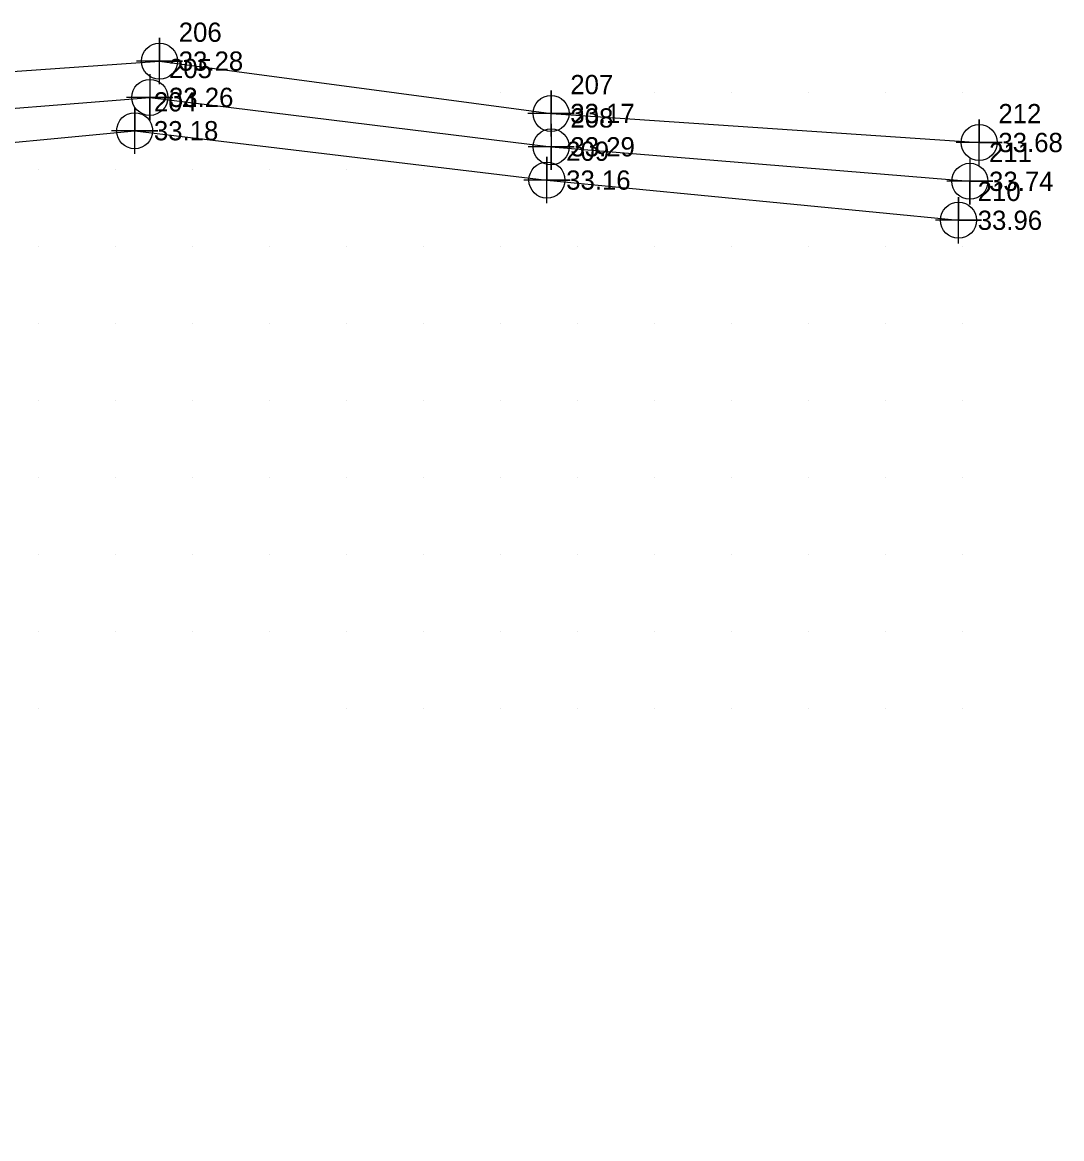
# Model space of a CAD drawing. Extents: x 2204340 to 2204783, y 268170 to 268760.
# Drawn here: x 2204647.9 to 2204782.9, y 268494.2 to 268639.1 of the extents above; entities that cross this region are included whole.
import ezdxf

# ---------------------------------------------------------------- set-up
doc = ezdxf.new("R2010")
doc.units = 0
for name, color, linetype in [('Exist DTM Crownline', 7, 'Continuous'), ('Exist DTM Crownline Cogo Elevation', 7, 'Continuous'), ('Exist DTM Crownline Cogo Number', 7, 'Continuous'), ('Exist DTM Crownline Cogo Point CELL', 7, 'Continuous'), ('Exist DTM QL2 LIDAR Elevation Point', 7, 'Continuous'), ('Exist Roads Soil', 7, 'Continuous'), ('Exist Roads Soil Cogo Elevation', 7, 'Continuous'), ('Exist Roads Soil Cogo Number', 7, 'Continuous'), ('Exist Roads Soil Cogo Point CELL', 7, 'Continuous')]:
    doc.layers.add(name, color=color, linetype=linetype)

msp = doc.modelspace()

# ---------------------------------------------------------------- linework, layer by layer
at = {"layer": 'Exist DTM Crownline'}
msp.add_lwpolyline([(2204544.57, 268496.57), (2204544.8, 268497.2), (2204557.39, 268525.73), (2204578.98, 268570.95), (2204607.65, 268611.86), (2204633.94, 268626.95), (2204664.49, 268629.4), (2204716.63, 268622.98), (2204771.01, 268618.5)], dxfattribs=at)
at = {"layer": 'Exist DTM Crownline Cogo Point CELL'}
for points in [[(2204664.49, 268632.4), (2204664.49, 268626.4), (2204664.49, 268629.4), (2204667.49, 268629.4), (2204661.49, 268629.4)], [(2204716.63, 268625.98), (2204716.63, 268619.98), (2204716.63, 268622.98), (2204719.63, 268622.98), (2204713.63, 268622.98)], [(2204771.01, 268621.5), (2204771.01, 268615.5), (2204771.01, 268618.5), (2204774.01, 268618.5), (2204768.01, 268618.5)]]:
    msp.add_lwpolyline(points, dxfattribs=at)
for centre in [(2204664.49, 268629.4), (2204716.63, 268622.98), (2204771.01, 268618.5)]:
    msp.add_circle(centre, 2.34, dxfattribs=at)
at = {"layer": 'Exist DTM QL2 LIDAR Elevation Point'}
for p, q in [((2204710, 268630), (2204710, 268630)), ((2204720, 268630), (2204720, 268630)), ((2204730, 268630), (2204730, 268630)), ((2204740, 268630), (2204740, 268630)), ((2204750, 268630), (2204750, 268630)), ((2204760, 268630), (2204760, 268630)), ((2204770, 268630), (2204770, 268630)), ((2204650, 268620), (2204650, 268620)), ((2204660, 268620), (2204660, 268620)), ((2204670, 268620), (2204670, 268620)), ((2204680, 268620), (2204680, 268620)), ((2204690, 268620), (2204690, 268620)), ((2204700, 268620), (2204700, 268620)), ((2204650, 268610), (2204650, 268610)), ((2204660, 268610), (2204660, 268610)), ((2204670, 268610), (2204670, 268610)), ((2204680, 268610), (2204680, 268610)), ((2204690, 268610), (2204690, 268610)), ((2204700, 268610), (2204700, 268610)), ((2204710, 268610), (2204710, 268610)), ((2204720, 268610), (2204720, 268610)), ((2204730, 268610), (2204730, 268610)), ((2204740, 268610), (2204740, 268610)), ((2204750, 268610), (2204750, 268610)), ((2204760, 268610), (2204760, 268610)), ((2204770, 268610), (2204770, 268610)), ((2204650, 268600), (2204650, 268600)), ((2204660, 268600), (2204660, 268600)), ((2204670, 268600), (2204670, 268600)), ((2204680, 268600), (2204680, 268600)), ((2204690, 268600), (2204690, 268600)), ((2204700, 268600), (2204700, 268600)), ((2204710, 268600), (2204710, 268600)), ((2204720, 268600), (2204720, 268600)), ((2204730, 268600), (2204730, 268600)), ((2204740, 268600), (2204740, 268600)), ((2204750, 268600), (2204750, 268600)), ((2204760, 268600), (2204760, 268600)), ((2204770, 268600), (2204770, 268600)), ((2204650, 268590), (2204650, 268590)), ((2204660, 268590), (2204660, 268590)), ((2204670, 268590), (2204670, 268590)), ((2204680, 268590), (2204680, 268590)), ((2204690, 268590), (2204690, 268590)), ((2204700, 268590), (2204700, 268590)), ((2204710, 268590), (2204710, 268590)), ((2204720, 268590), (2204720, 268590)), ((2204730, 268590), (2204730, 268590)), ((2204740, 268590), (2204740, 268590)), ((2204750, 268590), (2204750, 268590)), ((2204760, 268590), (2204760, 268590)), ((2204770, 268590), (2204770, 268590)), ((2204650, 268580), (2204650, 268580)), ((2204660, 268580), (2204660, 268580)), ((2204670, 268580), (2204670, 268580)), ((2204680, 268580), (2204680, 268580)), ((2204690, 268580), (2204690, 268580)), ((2204700, 268580), (2204700, 268580)), ((2204710, 268580), (2204710, 268580)), ((2204720, 268580), (2204720, 268580)), ((2204730, 268580), (2204730, 268580)), ((2204740, 268580), (2204740, 268580)), ((2204750, 268580), (2204750, 268580)), ((2204760, 268580), (2204760, 268580)), ((2204770, 268580), (2204770, 268580)), ((2204650, 268570), (2204650, 268570)), ((2204660, 268570), (2204660, 268570)), ((2204670, 268570), (2204670, 268570)), ((2204680, 268570), (2204680, 268570)), ((2204690, 268570), (2204690, 268570)), ((2204700, 268570), (2204700, 268570)), ((2204710, 268570), (2204710, 268570)), ((2204720, 268570), (2204720, 268570)), ((2204730, 268570), (2204730, 268570)), ((2204740, 268570), (2204740, 268570)), ((2204750, 268570), (2204750, 268570)), ((2204760, 268570), (2204760, 268570)), ((2204770, 268570), (2204770, 268570)), ((2204650, 268560), (2204650, 268560)), ((2204660, 268560), (2204660, 268560)), ((2204670, 268560), (2204670, 268560)), ((2204680, 268560), (2204680, 268560)), ((2204690, 268560), (2204690, 268560)), ((2204700, 268560), (2204700, 268560)), ((2204710, 268560), (2204710, 268560)), ((2204720, 268560), (2204720, 268560)), ((2204730, 268560), (2204730, 268560)), ((2204740, 268560), (2204740, 268560)), ((2204750, 268560), (2204750, 268560)), ((2204760, 268560), (2204760, 268560)), ((2204770, 268560), (2204770, 268560)), ((2204650, 268550), (2204650, 268550)), ((2204690, 268550), (2204690, 268550)), ((2204700, 268550), (2204700, 268550)), ((2204710, 268550), (2204710, 268550)), ((2204720, 268550), (2204720, 268550)), ((2204730, 268550), (2204730, 268550)), ((2204740, 268550), (2204740, 268550)), ((2204750, 268550), (2204750, 268550)), ((2204760, 268550), (2204760, 268550)), ((2204770, 268550), (2204770, 268550))]:
    msp.add_line(p, q, dxfattribs=at)
at = {"layer": 'Exist Roads Soil'}
for points in [[(2204539.85, 268499.13), (2204551.95, 268529.07), (2204571.26, 268573.83), (2204604.44, 268616.7), (2204631.8, 268631.71), (2204665.76, 268634.11), (2204716.61, 268627.31), (2204772.22, 268623.54)], [(2204549.08, 268494.18), (2204563.25, 268523.88), (2204586.27, 268566.28), (2204611.48, 268606.18), (2204635.18, 268622.47), (2204662.53, 268625.07), (2204716.08, 268618.66), (2204769.53, 268613.44)]]:
    msp.add_lwpolyline(points, dxfattribs=at)
at = {"layer": 'Exist Roads Soil Cogo Point CELL'}
for points in [[(2204665.76, 268631.11), (2204665.76, 268637.11), (2204665.76, 268634.11), (2204668.76, 268634.11), (2204662.76, 268634.11)], [(2204716.61, 268624.31), (2204716.61, 268630.31), (2204716.61, 268627.31), (2204719.61, 268627.31), (2204713.61, 268627.31)], [(2204662.53, 268622.07), (2204662.53, 268628.07), (2204662.53, 268625.07), (2204665.53, 268625.07), (2204659.53, 268625.07)], [(2204772.22, 268620.54), (2204772.22, 268626.54), (2204772.22, 268623.54), (2204775.22, 268623.54), (2204769.22, 268623.54)], [(2204716.08, 268615.66), (2204716.08, 268621.66), (2204716.08, 268618.66), (2204719.08, 268618.66), (2204713.08, 268618.66)], [(2204769.53, 268610.44), (2204769.53, 268616.44), (2204769.53, 268613.44), (2204772.53, 268613.44), (2204766.53, 268613.44)]]:
    msp.add_lwpolyline(points, dxfattribs=at)
for centre in [(2204665.76, 268634.11), (2204716.61, 268627.31), (2204662.53, 268625.07), (2204772.22, 268623.54), (2204716.08, 268618.66), (2204769.53, 268613.44)]:
    msp.add_circle(centre, 2.34, dxfattribs=at)

# ---------------------------------------------------------------- texts
at = {"layer": 'Exist DTM Crownline Cogo Elevation'}
for s, p in [('33.26', (2204666.99, 268628.15)), ('33.29', (2204719.13, 268621.73)), ('33.74', (2204773.51, 268617.25))]:
    msp.add_text(s, height=2.5, dxfattribs=at).set_placement(p)
at = {"layer": 'Exist DTM Crownline Cogo Number'}
for s, p in [('205', (2204666.99, 268631.9)), ('208', (2204719.13, 268625.48)), ('211', (2204773.51, 268621))]:
    msp.add_text(s, height=2.5, dxfattribs=at).set_placement(p)
at = {"layer": 'Exist Roads Soil Cogo Elevation'}
for s, p in [('33.28', (2204668.26, 268632.86)), ('33.17', (2204719.11, 268626.06)), ('33.18', (2204665.03, 268623.82)), ('33.68', (2204774.72, 268622.29)), ('33.16', (2204718.58, 268617.41)), ('33.96', (2204772.03, 268612.19))]:
    msp.add_text(s, height=2.5, dxfattribs=at).set_placement(p)
at = {"layer": 'Exist Roads Soil Cogo Number'}
for s, p in [('206', (2204668.26, 268636.61)), ('207', (2204719.11, 268629.81)), ('204', (2204665.03, 268627.57)), ('212', (2204774.72, 268626.04)), ('209', (2204718.58, 268621.16)), ('210', (2204772.03, 268615.94))]:
    msp.add_text(s, height=2.5, dxfattribs=at).set_placement(p)

doc.saveas('drawing.dxf')
